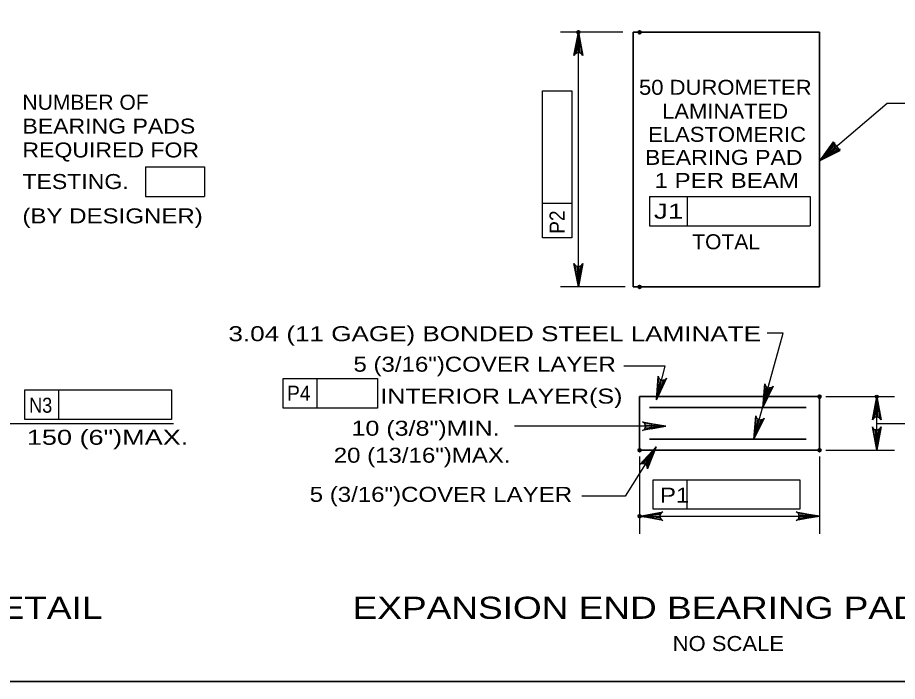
# Model space of a CAD drawing. Extents: x -11 to 79, y -154 to 0.
# Drawn here: x 42.01 to 49.06, y -43.25 to -37.93 of the extents above; entities that cross this region are included whole.
import ezdxf
from ezdxf.enums import TextEntityAlignment as Align

# ---------------------------------------------------------------- set-up
doc = ezdxf.new("R2010")
doc.units = 0
doc.header["$LTSCALE"] = 0.048
doc.header["$PDMODE"] = 32
doc.header["$PDSIZE"] = 0.024
for name, color, linetype, lineweight in [('1', 7, 'Continuous', 25), ('2', 7, 'Continuous', 35), ('3', 7, 'Continuous', 25), ('4', 7, 'Continuous', 25), ('5', 7, 'Continuous', 25), ('6', 7, 'Continuous', 25), ('7', 7, 'Continuous', 35)]:
    doc.layers.add(name, color=color, linetype=linetype, lineweight=lineweight)

msp = doc.modelspace()

# ---------------------------------------------------------------- hatches: boundary and pattern name
at = {"layer": '2'}
for points in [[(46.4865, -38.14675), (46.518, -38.14675), (46.50225, -38.05225)], [(48.43442, -39.08083), (48.60083, -38.99875), (48.54258, -38.93008)], [(46.4865, -39.99592), (46.518, -39.99592), (46.50225, -40.09042)], [(47.0955, -41.91), (47.0955, -41.94417), (46.99317, -41.92708)], [(48.33217, -41.91), (48.33217, -41.94417), (48.43442, -41.92708)]]:
    msp.add_hatch(color=256, dxfattribs=at).paths.add_polyline_path(points)
at = {"layer": '3'}
for points in [[(47.16992, -40.8995), (47.13692, -40.891), (47.12792, -40.99433)], [(48.87558, -41.07692), (48.90967, -41.07692), (48.89267, -40.97458)], [(48.87558, -41.29675), (48.90967, -41.29675), (48.89267, -41.39908)], [(47.08475, -41.46817), (47.05583, -41.45008), (47.12458, -41.37242)]]:
    msp.add_hatch(color=256, dxfattribs=at).paths.add_polyline_path(points)
at = {"layer": '5'}
for points in [[(48.02942, -40.94708), (47.99142, -40.93658), (47.97892, -41.05567)], [(47.08533, -41.187), (47.08533, -41.22633), (47.20342, -41.20667)], [(47.95592, -41.20292), (47.918, -41.19242), (47.9055, -41.3115)]]:
    msp.add_hatch(color=256, dxfattribs=at).paths.add_polyline_path(points)

# ---------------------------------------------------------------- linework, layer by layer
at = {"layer": '1', "lineweight": 35}
msp.add_lwpolyline([(35.75, -43.25), (67.25, -43.25), (67.25, -22.75), (35.75, -22.75)], close=True, dxfattribs=at)
at = {"layer": '2', "lineweight": 25}
for p, q in [((46.85917, -38.05225), (46.3605, -38.05225)), ((48.43442, -39.08083), (48.977, -38.6205)), ((48.977, -38.6205), (49.11708, -38.6205)), ((46.87792, -40.09042), (46.3605, -40.09042)), ((46.99317, -41.44825), (46.99317, -42.06875)), ((48.43442, -41.44825), (48.43442, -42.06875)), ((46.99317, -41.92708), (48.43442, -41.92708))]:
    msp.add_line(p, q, dxfattribs=at)
for points in [[(46.50225, -38.05225), (46.53717, -38.23867), (46.52725, -38.22433), (46.51475, -38.21692), (46.50225, -38.21475), (46.48975, -38.21692), (46.47725, -38.22433), (46.46733, -38.23867), (46.50225, -38.05225), (46.47725, -38.22433), (46.48975, -38.21692), (46.50225, -38.05225), (46.50225, -38.21475), (46.51475, -38.21692), (46.50225, -38.05225), (46.52725, -38.22433)], [(48.43442, -39.08083), (48.55392, -38.93358), (48.54942, -38.9505), (48.55192, -38.96475), (48.55833, -38.97567), (48.56808, -38.98383), (48.58175, -38.98858), (48.59917, -38.98692), (48.43442, -39.08083), (48.58175, -38.98858), (48.56808, -38.98383), (48.43442, -39.08083), (48.55833, -38.97567), (48.55192, -38.96475), (48.43442, -39.08083), (48.54942, -38.9505)], [(46.50225, -40.09042), (46.46733, -39.904), (46.47725, -39.91833), (46.48975, -39.92575), (46.50225, -39.92792), (46.51475, -39.92575), (46.52725, -39.91833), (46.53717, -39.904), (46.50225, -40.09042), (46.52725, -39.91833), (46.51475, -39.92575), (46.50225, -40.09042), (46.50225, -39.92792), (46.48975, -39.92575), (46.50225, -40.09042), (46.47725, -39.91833)], [(47.12792, -40.99433), (47.14058, -40.80508), (47.14667, -40.8215), (47.15692, -40.83175), (47.16842, -40.837), (47.18108, -40.838), (47.19508, -40.834), (47.20825, -40.8225), (47.12792, -40.99433), (47.19508, -40.834), (47.18108, -40.838), (47.12792, -40.99433), (47.16842, -40.837), (47.15692, -40.83175), (47.12792, -40.99433), (47.14667, -40.8215)], [(47.97892, -41.05567), (47.99492, -40.86667), (48.00067, -40.88317), (48.01075, -40.89367), (48.02225, -40.89908), (48.03483, -40.90033), (48.04892, -40.8965), (48.06233, -40.88533), (47.97892, -41.05567), (48.04892, -40.8965), (48.03483, -40.90033), (47.97892, -41.05567), (48.02225, -40.89908), (48.01075, -40.89367), (47.97892, -41.05567), (48.00067, -40.88317)], [(48.89267, -40.96983), (48.92758, -41.15625), (48.91767, -41.14192), (48.90517, -41.1345), (48.89267, -41.13233), (48.88017, -41.1345), (48.86767, -41.14192), (48.85775, -41.15625), (48.89267, -40.96983), (48.86767, -41.14192), (48.88017, -41.1345), (48.89267, -40.96983), (48.89267, -41.13233), (48.90517, -41.1345), (48.89267, -40.96983), (48.91767, -41.14192)], [(47.90808, -41.3115), (47.92408, -41.1225), (47.92992, -41.139), (47.93992, -41.1495), (47.95142, -41.15492), (47.96408, -41.15617), (47.97808, -41.15233), (47.9915, -41.14117), (47.90808, -41.3115), (47.97808, -41.15233), (47.96408, -41.15617), (47.90808, -41.3115), (47.95142, -41.15492), (47.93992, -41.1495), (47.90808, -41.3115), (47.92992, -41.139)], [(47.20342, -41.20667), (47.017, -41.24158), (47.03133, -41.23167), (47.03875, -41.21917), (47.04092, -41.20667), (47.03875, -41.19417), (47.03133, -41.18167), (47.017, -41.17175), (47.20342, -41.20667), (47.03133, -41.18167), (47.03875, -41.19417), (47.20342, -41.20667), (47.04092, -41.20667), (47.03875, -41.21917), (47.20342, -41.20667), (47.03133, -41.23167)], [(48.89267, -41.39908), (48.85775, -41.21267), (48.86767, -41.227), (48.88017, -41.23442), (48.89267, -41.23658), (48.90517, -41.23442), (48.91767, -41.227), (48.92758, -41.21267), (48.89267, -41.39908), (48.91767, -41.227), (48.90517, -41.23442), (48.89267, -41.39908), (48.89267, -41.23658), (48.88017, -41.23442), (48.89267, -41.39908), (48.86767, -41.227)], [(47.12458, -41.37242), (47.05533, -41.549), (47.0545, -41.5315), (47.04783, -41.51858), (47.03842, -41.51017), (47.02667, -41.50533), (47.01208, -41.505), (46.99608, -41.51192), (47.12458, -41.37242), (47.01208, -41.505), (47.02667, -41.50533), (47.12458, -41.37242), (47.03842, -41.51017), (47.04783, -41.51858), (47.12458, -41.37242), (47.0545, -41.5315)], [(46.99317, -41.92708), (47.17958, -41.89217), (47.16525, -41.90208), (47.15783, -41.91458), (47.15567, -41.92708), (47.15783, -41.93958), (47.16525, -41.95208), (47.17958, -41.962), (46.99317, -41.92708), (47.16525, -41.95208), (47.15783, -41.93958), (46.99317, -41.92708), (47.15567, -41.92708), (47.15783, -41.91458), (46.99317, -41.92708), (47.16525, -41.90208)], [(48.43442, -41.92708), (48.248, -41.962), (48.26233, -41.95208), (48.26975, -41.93958), (48.27192, -41.92708), (48.26975, -41.91458), (48.26233, -41.90208), (48.248, -41.89217), (48.43442, -41.92708), (48.26233, -41.90208), (48.26975, -41.91458), (48.43442, -41.92708), (48.27192, -41.92708), (48.26975, -41.93958), (48.43442, -41.92708), (48.26233, -41.95208)]]:
    msp.add_lwpolyline(points, dxfattribs=at)
for points in [[(46.4865, -38.14675), (46.518, -38.14675), (46.50225, -38.05225)], [(48.43442, -39.08083), (48.60083, -38.99875), (48.54258, -38.93008)], [(46.4865, -39.99592), (46.518, -39.99592), (46.50225, -40.09042)], [(47.0955, -41.91), (47.0955, -41.94417), (46.99317, -41.92708)], [(48.33217, -41.91), (48.33217, -41.94417), (48.43442, -41.92708)]]:
    msp.add_lwpolyline(points, close=True, dxfattribs=at)
at = {"layer": '3'}
for p, q in [((46.50225, -40.09042), (46.50225, -38.05225)), ((46.21483, -39.69758), (46.21483, -38.52175)), ((46.21483, -38.52175), (46.45108, -38.52175)), ((46.45108, -38.52175), (46.45108, -39.69758)), ((43.03608, -39.12983), (43.50783, -39.12983)), ((43.03608, -39.12983), (43.03608, -39.36608)), ((43.50783, -39.12983), (43.50783, -39.36608)), ((43.03608, -39.36608), (43.50783, -39.36608)), ((47.07208, -39.36633), (48.35808, -39.36633)), ((47.07208, -39.36633), (47.07208, -39.60258)), ((47.3745, -39.36633), (47.3745, -39.60258)), ((48.35808, -39.36633), (48.35808, -39.60258)), ((46.45108, -39.42375), (46.21483, -39.42375)), ((47.07208, -39.60258), (48.35808, -39.60258)), ((46.45108, -39.69758), (46.21483, -39.69758)), ((47.19683, -40.72683), (46.86717, -40.72683)), ((47.12792, -40.99433), (47.19683, -40.72683)), ((44.13658, -40.825), (44.89292, -40.825)), ((44.13658, -41.06117), (44.13658, -40.825)), ((44.41042, -41.06117), (44.41042, -40.825)), ((44.89292, -40.825), (44.89292, -41.06117)), ((42.06808, -40.91542), (43.24392, -40.91542)), ((42.06808, -41.15158), (42.06808, -40.91542)), ((42.34192, -41.15158), (42.34192, -40.91542)), ((43.24392, -40.91542), (43.24392, -41.15158)), ((48.48367, -40.96983), (49.03425, -40.96983)), ((48.89267, -41.39908), (48.89267, -40.96983)), ((44.89292, -41.06117), (44.13658, -41.06117)), ((43.24392, -41.15158), (42.06808, -41.15158)), ((41.75325, -41.18442), (43.2595, -41.18442)), ((48.89267, -41.18442), (50.39892, -41.18442)), ((47.12458, -41.37242), (46.87783, -41.76675)), ((48.48367, -41.39908), (49.03425, -41.39908)), ((47.1005, -41.87167), (47.1005, -41.63542)), ((47.1005, -41.63542), (48.27625, -41.63542)), ((47.37425, -41.87167), (47.37425, -41.63542)), ((48.27625, -41.63542), (48.27625, -41.87167)), ((46.87783, -41.76675), (46.5295, -41.76675)), ((48.27625, -41.87167), (47.1005, -41.87167))]:
    msp.add_line(p, q, dxfattribs=at)
for points in [[(47.16992, -40.8995), (47.13692, -40.891), (47.12792, -40.99433)], [(48.87558, -41.07692), (48.90967, -41.07692), (48.89267, -40.97458)], [(48.87558, -41.29675), (48.90967, -41.29675), (48.89267, -41.39908)], [(47.08475, -41.46817), (47.05583, -41.45008), (47.12458, -41.37242)]]:
    msp.add_lwpolyline(points, close=True, dxfattribs=at)
msp.add_point((48.89267, -40.96983), dxfattribs=at)
at = {"layer": '4', "lineweight": 35}
for p, q in [((46.94058, -38.05225), (46.94058, -40.09042)), ((46.94058, -38.05225), (48.43442, -38.05225)), ((48.43442, -38.05225), (48.43442, -40.09042)), ((46.94058, -40.09042), (48.43442, -40.09042)), ((48.43442, -40.96983), (46.99317, -40.96983)), ((46.99317, -40.96983), (46.99317, -41.39908)), ((48.43442, -41.39908), (48.43442, -40.96983)), ((48.3275, -41.05567), (47.07267, -41.05567)), ((48.3275, -41.3115), (47.07267, -41.3115)), ((46.99317, -41.39908), (48.43442, -41.39908))]:
    msp.add_line(p, q, dxfattribs=at)
at = {"layer": '5'}
for p, q in [((47.90808, -41.3115), (48.14358, -40.46058)), ((47.20342, -41.20667), (45.992, -41.20667))]:
    msp.add_line(p, q, dxfattribs=at)
for points in [[(48.02942, -40.94708), (47.99142, -40.93658), (47.97892, -41.05567)], [(47.08533, -41.187), (47.08533, -41.22633), (47.20342, -41.20667)], [(47.95592, -41.20292), (47.918, -41.19242), (47.9055, -41.3115)]]:
    msp.add_lwpolyline(points, close=True, dxfattribs=at)
at = {"layer": '6'}
msp.add_line((48.14358, -40.46058), (48.01525, -40.46058), dxfattribs=at)
at = {"layer": '7'}
for p in [(46.50225, -38.05225), (46.99317, -38.05225), (46.99317, -40.09042), (48.43442, -40.96983), (46.99317, -41.39908), (48.43442, -41.39908), (46.99317, -41.92708)]:
    msp.add_point(p, dxfattribs=at)

# ---------------------------------------------------------------- texts
at = {"layer": '3'}
for s, height, width, p in [('50 DUROMETER', 0.12, 1.1, (47.67954, -38.55258)), ('LAMINATED', 0.12, 1.1, (47.67788, -38.74458)), ('ELASTOMERIC', 0.12, 1.1, (47.69375, -38.92917)), ('BEARING PAD', 0.12, 1.15, (47.66708, -39.11375)), ('1 PER BEAM', 0.12, 1.2, (47.69058, -39.29842)), ('TOTAL', 0.12, 1.05, (47.68621, -39.78942)), ('3.04 (11 GAGE) BONDED STEEL LAMINATE', 0.12, 1.3, (45.8325, -40.52567)), ('5 (3/16")COVER LAYER', 0.12, 1.2, (45.75167, -40.76983)), ('P4', 0.12, 0.95, (44.26304, -41.00183)), ('INTERIOR LAYER(S)', 0.12, 1.25, (45.88587, -41.0255)), ('N3', 0.12, 0.9, (42.19529, -41.0985)), ('10 (3/8")MIN.', 0.12, 1.25, (45.27821, -41.2825)), ('150 (6")MAX.', 0.12, 1.35, (42.73142, -41.35533)), ('20 (13/16")MAX.', 0.12, 1.2, (45.25121, -41.49875)), ('5 (3/16")COVER LAYER', 0.12, 1.2, (45.40125, -41.81217)), ('P1', 0.12, 1.2, (47.27354, -41.81842)), ('FIXED END BEARING PAD DETAIL', 0.1772, 1.25, (40.28683, -42.749)), ('EXPANSION END BEARING PAD DETAIL', 0.1772, 1.25, (47.52546, -42.749)), ('NO SCALE', 0.12, 1.1, (47.70379, -43.00658))]:
    msp.add_text(s, height=height, dxfattribs=dict(at, width=width)).set_placement(p, align=Align.CENTER)
for s, width, p in [('NUMBER OF', 1.05, (42.04925, -38.67192)), ('BEARING PADS', 1.15, (42.04925, -38.86317)), ('REQUIRED FOR', 1.15, (42.04925, -39.05433)), ('TESTING.', 1.15, (42.04925, -39.307)), ('(BY DESIGNER)', 1.2, (42.04925, -39.582))]:
    msp.add_text(s, height=0.12, dxfattribs=dict(at, width=width)).set_placement(p)
for s, rotation, width, p in [('J1', 359.938, 1.4, (47.22577, -39.54455)), ('P2', 90, 0.95, (46.39175, -39.57212))]:
    msp.add_text(s, height=0.12, rotation=rotation, dxfattribs=dict(at, width=width)).set_placement(p, align=Align.CENTER)

doc.saveas('drawing.dxf')
